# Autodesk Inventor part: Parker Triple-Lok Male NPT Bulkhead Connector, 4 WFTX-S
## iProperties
Shininess: 27.0
Category: Hydraulics
Created: 2001-03
Part Number: Parker Triple-Lok Male NPT Bulkhead Connector, 4 WFTX-S
Document SubType Name: Modeling
Designer: QBZ
Material: Steel, Mild
Description: Parker Triple-Lok Male NPT Bulkhead Connector, 4 WFTX-S
Catalog Web Link: http://www.aeroquip.com
Density: 0.0
Volumn: 0.0
Area: 0.0
PropertySet Name: Model Information
Control State: 0
Master: False
Checked Out: False
Last Check In Date: 2003-09-27
Last Check In By: Charles Bliss
Title: JIC Bulkhead Union
Author: QBZ
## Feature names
1. Revolution1
2. Long end [Hole]
3. Short End [Hole]
4. Revolution2
